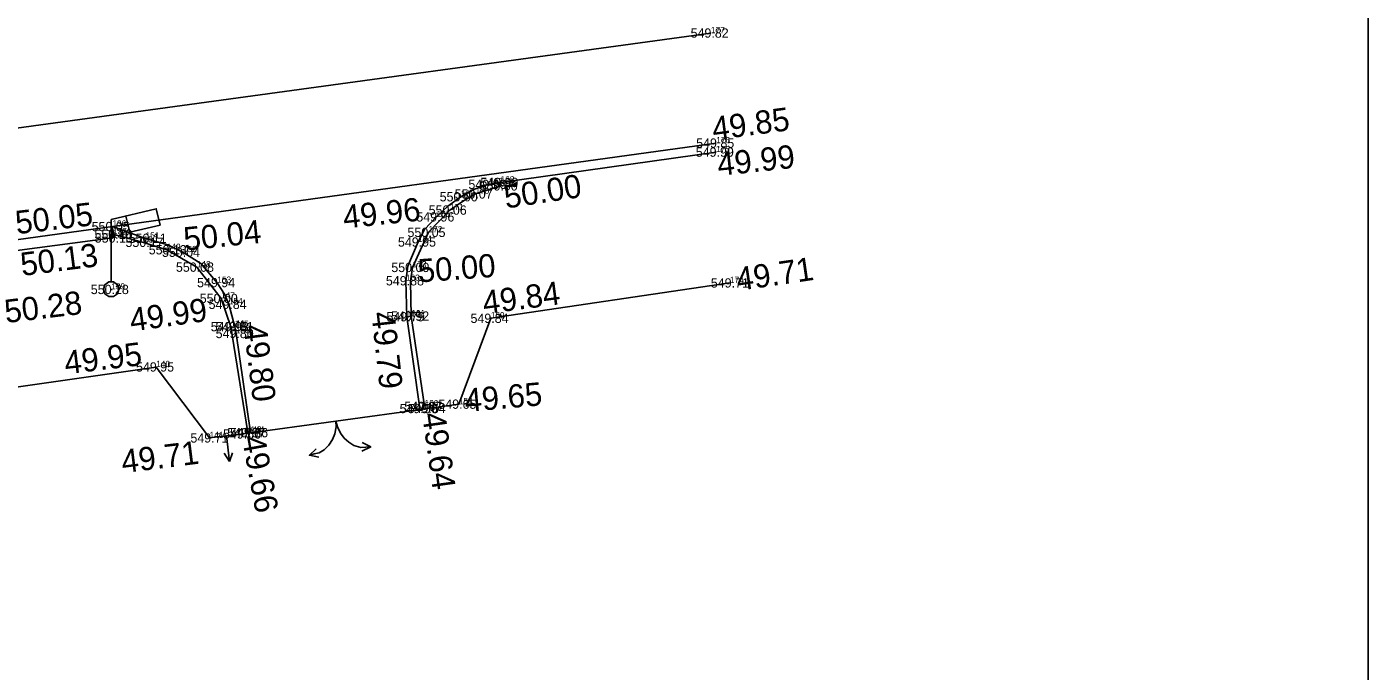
# Model space of a CAD drawing. Extents: x -866693 to -866303, y -1041966 to -1040244.
# Drawn here: x -866525.8 to -866482.52, y -1040296.75 to -1040275.97 of the extents above; entities that cross this region are included whole.
import ezdxf

# ---------------------------------------------------------------- set-up
doc = ezdxf.new("R2010")
doc.units = 0
for name, color, linetype in [('1 hrana zpevněné komunikace-plocha', 7, 'Continuous'), ('10 plot drátěný', 7, 'Continuous'), ('2 hrana nezpevněné komunikace-plocha', 7, 'Continuous'), ('3 osa komunikace', 7, 'Continuous'), ('33 vstup', 7, 'Continuous'), ('34 vrata-vjezd', 7, 'Continuous'), ('43 lampa', 7, 'Continuous'), ('5 obrubník nahoře (chodník)', 7, 'Continuous'), ('Bod', 7, 'Continuous'), ('Formát', 7, 'Continuous'), ('Nadmořská výška', 7, 'Continuous'), ('Nadmořská výška_tisk', 7, 'Continuous'), ('Číslo bodu', 7, 'Continuous')]:
    doc.layers.add(name, color=color, linetype=linetype)

msp = doc.modelspace()

# ---------------------------------------------------------------- linework, layer by layer
at = {"layer": '1 hrana zpevněné komunikace-plocha'}
msp.add_lwpolyline([(-866503.553, -1040279.722), (-866523.034, -1040282.41), (-866541.374, -1040284.946), (-866561.808, -1040287.782), (-866574.398, -1040289.556), (-866602.398, -1040293.439), (-866619.972, -1040295.863), (-866638.769, -1040298.486), (-866650.196, -1040300.008), (-866657.766, -1040301.183), (-866663.405, -1040303.497), (-866666.7, -1040305.877), (-866670.718, -1040310.555), (-866673.161, -1040315.92), (-866674.075, -1040319.269), (-866673.907, -1040325.701)], dxfattribs=at)
at = {"layer": '10 plot drátěný'}
for points in [[(-866503.113, -1040284.232), (-866510.828, -1040285.371), (-866511.86, -1040288.144), (-866512.845, -1040288.278)], [(-866519.897, -1040289.231), (-866521.621, -1040286.942), (-866544.513, -1040290.213), (-866543.988, -1040294.889)]]:
    msp.add_lwpolyline(points, dxfattribs=at)
at = {"layer": '2 hrana nezpevněné komunikace-plocha'}
for points in [[(-866510.513, -1040280.987), (-866510.888, -1040281.049), (-866511.388, -1040281.219), (-866511.79, -1040281.449), (-866512.216, -1040281.757), (-866512.574, -1040282.102), (-866512.967, -1040282.503), (-866513.171, -1040282.909), (-866513.503, -1040283.69), (-866513.564, -1040284.16), (-866513.541, -1040285.321), (-866513.113, -1040288.281)], [(-866518.579, -1040289.058), (-866519.039, -1040285.858), (-866519.085, -1040285.642), (-866519.28, -1040284.92), (-866519.42, -1040284.597), (-866519.651, -1040284.223), (-866520.186, -1040283.608), (-866520.759, -1040283.236), (-866521.251, -1040283.004), (-866521.964, -1040282.794), (-866523.034, -1040282.41)]]:
    msp.add_lwpolyline(points, dxfattribs=at)
at = {"layer": '3 osa komunikace'}
msp.add_lwpolyline([(-866675.016, -1040299.403), (-866658.944, -1040297.823), (-866639.253, -1040295.089), (-866620.168, -1040292.742), (-866603.167, -1040290.212), (-866574.251, -1040285.999), (-866539.891, -1040281.121), (-866503.725, -1040276.174)], dxfattribs=at)
at = {"layer": '33 vstup'}
for p, q in [((-866519.897, -1040289.231), (-866518.804, -1040289.101)), ((-866519.256, -1040289.986), (-866519.351, -1040289.166)), ((-866519.256, -1040289.986), (-866519.427, -1040289.725)), ((-866519.256, -1040289.986), (-866519.161, -1040289.706))]:
    msp.add_line(p, q, dxfattribs=at)
at = {"layer": '34 vrata-vjezd'}
msp.add_line((-866518.804, -1040289.101), (-866512.845, -1040288.278), dxfattribs=at)
for points in [[(-866514.701, -1040289.519), (-866515.02, -1040289.533), (-866515.245, -1040289.473), (-866515.405, -1040289.371), (-866515.558, -1040289.233), (-866515.68, -1040289.076), (-866515.775, -1040288.867), (-866515.825, -1040288.687), (-866515.819, -1040288.873), (-866515.859, -1040289.098), (-866515.934, -1040289.285), (-866516.048, -1040289.465), (-866516.2, -1040289.612), (-866516.368, -1040289.708), (-866516.524, -1040289.747), (-866516.68, -1040289.786)], [(-866514.984, -1040289.659), (-866514.701, -1040289.519), (-866514.972, -1040289.38)], [(-866516.37, -1040289.845), (-866516.68, -1040289.786), (-866516.457, -1040289.579)]]:
    msp.add_lwpolyline(points, dxfattribs=at)
at = {"layer": '43 lampa'}
for points in [[(-866523.072, -1040284.199), (-866522.997, -1040284.199), (-866522.872, -1040284.289), (-866522.822, -1040284.434), (-866522.872, -1040284.579), (-866522.997, -1040284.669), (-866523.152, -1040284.669), (-866523.277, -1040284.579), (-866523.327, -1040284.434), (-866523.277, -1040284.289), (-866523.152, -1040284.199), (-866523.072, -1040284.199), (-866523.072, -1040282.189), (-866521.622, -1040281.839), (-866521.497, -1040282.364), (-866522.472, -1040282.589), (-866522.597, -1040282.074)], [(-866523.102, -1040284.439), (-866523.042, -1040284.439)]]:
    msp.add_lwpolyline(points, dxfattribs=at)
at = {"layer": '5 obrubník nahoře (chodník)'}
for p, q in [((-866510.513, -1040280.987), (-866503.562, -1040280.008)), ((-866523.016, -1040282.78), (-866541.009, -1040285.146))]:
    msp.add_line(p, q, dxfattribs=at)
for points in [[(-866510.513, -1040280.987), (-866510.498, -1040281.096), (-866511.323, -1040281.358), (-866511.703, -1040281.581), (-866512.148, -1040281.881), (-866512.837, -1040282.596), (-866513.349, -1040283.73), (-866513.413, -1040284.174), (-866513.393, -1040285.304), (-866512.963, -1040288.206)], [(-866523.016, -1040282.78), (-866523.016, -1040282.78), (-866523.018, -1040282.657), (-866523.034, -1040282.41)], [(-866518.665, -1040289.058), (-866519.211, -1040285.641), (-866519.529, -1040284.728), (-866520.312, -1040283.722), (-866521.279, -1040283.162), (-866522.028, -1040282.923), (-866523.018, -1040282.657)]]:
    msp.add_lwpolyline(points, dxfattribs=at)
at = {"layer": 'Bod'}
for p, q in [((-866503.725, -1040276.174), (-866503.725, -1040276.174)), ((-866503.553, -1040279.722), (-866503.553, -1040279.722)), ((-866503.562, -1040280.008), (-866503.562, -1040280.008)), ((-866510.888, -1040281.049), (-866510.888, -1040281.049)), ((-866510.513, -1040280.987), (-866510.513, -1040280.987)), ((-866510.498, -1040281.096), (-866510.498, -1040281.096)), ((-866511.79, -1040281.449), (-866511.79, -1040281.449)), ((-866511.323, -1040281.358), (-866511.323, -1040281.358)), ((-866512.574, -1040282.102), (-866512.574, -1040282.102)), ((-866512.148, -1040281.881), (-866512.148, -1040281.881)), ((-866523.034, -1040282.41), (-866523.034, -1040282.41)), ((-866523.018, -1040282.657), (-866523.018, -1040282.657)), ((-866523.016, -1040282.78), (-866523.016, -1040282.78)), ((-866522.028, -1040282.923), (-866522.028, -1040282.923)), ((-866521.964, -1040282.794), (-866521.964, -1040282.794)), ((-866513.171, -1040282.909), (-866513.171, -1040282.909)), ((-866512.837, -1040282.596), (-866512.837, -1040282.596)), ((-866521.279, -1040283.162), (-866521.279, -1040283.162)), ((-866520.759, -1040283.236), (-866520.759, -1040283.236)), ((-866520.312, -1040283.722), (-866520.312, -1040283.722)), ((-866513.349, -1040283.73), (-866513.349, -1040283.73)), ((-866519.651, -1040284.223), (-866519.651, -1040284.223)), ((-866513.564, -1040284.16), (-866513.564, -1040284.16)), ((-866503.113, -1040284.232), (-866503.113, -1040284.232)), ((-866523.072, -1040284.439), (-866523.072, -1040284.439)), ((-866519.529, -1040284.728), (-866519.529, -1040284.728)), ((-866519.28, -1040284.92), (-866519.28, -1040284.92)), ((-866513.541, -1040285.321), (-866513.541, -1040285.321)), ((-866513.393, -1040285.304), (-866513.393, -1040285.304)), ((-866510.828, -1040285.371), (-866510.828, -1040285.371)), ((-866519.211, -1040285.641), (-866519.211, -1040285.641)), ((-866519.085, -1040285.642), (-866519.085, -1040285.642)), ((-866519.039, -1040285.858), (-866519.039, -1040285.858)), ((-866521.621, -1040286.942), (-866521.621, -1040286.942)), ((-866512.963, -1040288.206), (-866512.963, -1040288.206)), ((-866511.86, -1040288.144), (-866511.86, -1040288.144)), ((-866513.113, -1040288.281), (-866513.113, -1040288.281)), ((-866512.845, -1040288.278), (-866512.845, -1040288.278)), ((-866518.665, -1040289.058), (-866518.665, -1040289.058)), ((-866518.579, -1040289.058), (-866518.579, -1040289.058)), ((-866519.897, -1040289.231), (-866519.897, -1040289.231)), ((-866518.804, -1040289.101), (-866518.804, -1040289.101))]:
    msp.add_line(p, q, dxfattribs=at)
at = {"layer": 'Formát'}
msp.add_lwpolyline([(-866692.523, -1040244.107), (-866482.523, -1040244.107), (-866482.523, -1040541.107), (-866692.523, -1040541.107)], close=True, dxfattribs=at)

# ---------------------------------------------------------------- texts
at = {"layer": 'Nadmořská výška'}
for s, p in [('549.82', (-866504.381, -1040276.32)), ('549.85', (-866504.201, -1040279.87)), ('549.99', (-866504.214, -1040280.16)), ('549.99', (-866511.164, -1040281.14)), ('550.00', (-866512.477, -1040281.6)), ('550.07', (-866511.995, -1040281.51)), ('549.96', (-866511.55, -1040281.2)), ('550.00', (-866511.187, -1040281.25)), ('550.06', (-866512.832, -1040282.03)), ('549.96', (-866513.23, -1040282.25)), ('550.05', (-866523.705, -1040282.56)), ('550.10', (-866523.615, -1040282.81)), ('550.05', (-866513.515, -1040282.75)), ('550.13', (-866523.603, -1040282.93)), ('550.17', (-866522.613, -1040283.07)), ('550.11', (-866522.51, -1040282.94)), ('550.13', (-866521.863, -1040283.31)), ('549.95', (-866513.823, -1040283.06)), ('550.04', (-866521.435, -1040283.39)), ('550.08', (-866520.985, -1040283.87)), ('550.00', (-866514.037, -1040283.88)), ('550.28', (-866523.732, -1040284.59)), ('549.94', (-866520.303, -1040284.37)), ('549.88', (-866514.211, -1040284.31)), ('549.71', (-866503.728, -1040284.38)), ('550.00', (-866520.217, -1040284.88)), ('549.84', (-866519.931, -1040285.07)), ('549.79', (-866514.193, -1040285.47)), ('549.92', (-866514.043, -1040285.45)), ('549.93', (-866519.863, -1040285.79)), ('549.81', (-866519.708, -1040285.79)), ('549.84', (-866511.481, -1040285.52)), ('549.80', (-866519.704, -1040286.01)), ('549.95', (-866522.273, -1040287.09)), ('549.56', (-866513.769, -1040288.43)), ('549.67', (-866513.619, -1040288.36)), ('549.64', (-866513.509, -1040288.43)), ('549.65', (-866512.519, -1040288.29)), ('549.71', (-866520.518, -1040289.38)), ('549.66', (-866519.467, -1040289.25)), ('549.67', (-866519.329, -1040289.21)), ('549.56', (-866519.239, -1040289.21))]:
    msp.add_text(s, height=0.3, dxfattribs=at).set_placement(p)
at = {"layer": 'Nadmořská výška_tisk'}
for s, rotation, p in [('49.85', 7.5108, (-866503.639, -1040279.629)), ('49.99', 6.173, (-866503.481, -1040280.782)), ('50.00', 8.6843, (-866510.34, -1040281.833)), ('50.05', 6.6575, (-866526.123, -1040282.659)), ('49.96', 5.9672, (-866515.559, -1040282.477)), ('50.04', 5.7408, (-866520.701, -1040283.187)), ('50.13', 7.3246, (-866525.951, -1040284.007)), ('50.00', 4.2383, (-866513.153, -1040284.216)), ('49.71', 8.2165, (-866502.856, -1040284.488)), ('49.84', 7.4577, (-866511.042, -1040285.24)), ('50.28', 6.8568, (-866526.471, -1040285.526)), ('49.99', 7.9593, (-866522.424, -1040285.8)), ('49.79', 276.358, (-866514.684, -1040285.193)), ('49.80', 277.174, (-866518.809, -1040285.612)), ('49.95', 6.8696, (-866524.54, -1040287.179)), ('49.65', 5.0612, (-866511.642, -1040288.394)), ('49.64', 277.9857, (-866513.046, -1040288.452)), ('49.71', 7.0959, (-866522.7, -1040290.367)), ('49.66', 280.369, (-866518.859, -1040289.223))]:
    msp.add_text(s, height=0.75, rotation=rotation, dxfattribs=at).set_placement(p)
at = {"layer": 'Číslo bodu'}
for s, p in [('177', (-866503.725, -1040276.174)), ('176', (-866503.553, -1040279.722)), ('175', (-866503.562, -1040280.008)), ('167', (-866510.888, -1040281.049)), ('168', (-866510.513, -1040280.987)), ('166', (-866511.79, -1040281.449)), ('170', (-866511.323, -1040281.358)), ('169', (-866510.498, -1040281.096)), ('171', (-866512.148, -1040281.881)), ('165', (-866512.574, -1040282.102)), ('136', (-866523.034, -1040282.41)), ('137', (-866523.018, -1040282.657)), ('138', (-866523.016, -1040282.78)), ('151', (-866521.964, -1040282.794)), ('172', (-866512.837, -1040282.596)), ('150', (-866522.028, -1040282.923)), ('149', (-866521.279, -1040283.162)), ('164', (-866513.171, -1040282.909)), ('152', (-866520.759, -1040283.236)), ('148', (-866520.312, -1040283.722)), ('173', (-866513.349, -1040283.73)), ('139', (-866523.072, -1040284.439)), ('153', (-866519.651, -1040284.223)), ('163', (-866513.564, -1040284.16)), ('174', (-866503.113, -1040284.232)), ('147', (-866519.529, -1040284.728)), ('154', (-866519.28, -1040284.92)), ('162', (-866513.541, -1040285.321)), ('161', (-866513.393, -1040285.304)), ('159', (-866510.828, -1040285.371)), ('146', (-866519.211, -1040285.641)), ('145', (-866519.085, -1040285.642)), ('155', (-866519.039, -1040285.858)), ('140', (-866521.621, -1040286.942)), ('156', (-866513.113, -1040288.281)), ('160', (-866512.963, -1040288.206)), ('157', (-866512.845, -1040288.278)), ('158', (-866511.86, -1040288.144)), ('141', (-866519.897, -1040289.231)), ('142', (-866518.804, -1040289.101)), ('143', (-866518.665, -1040289.058)), ('144', (-866518.579, -1040289.058))]:
    msp.add_text(s, height=0.2, dxfattribs=at).set_placement(p)

doc.saveas('drawing.dxf')
